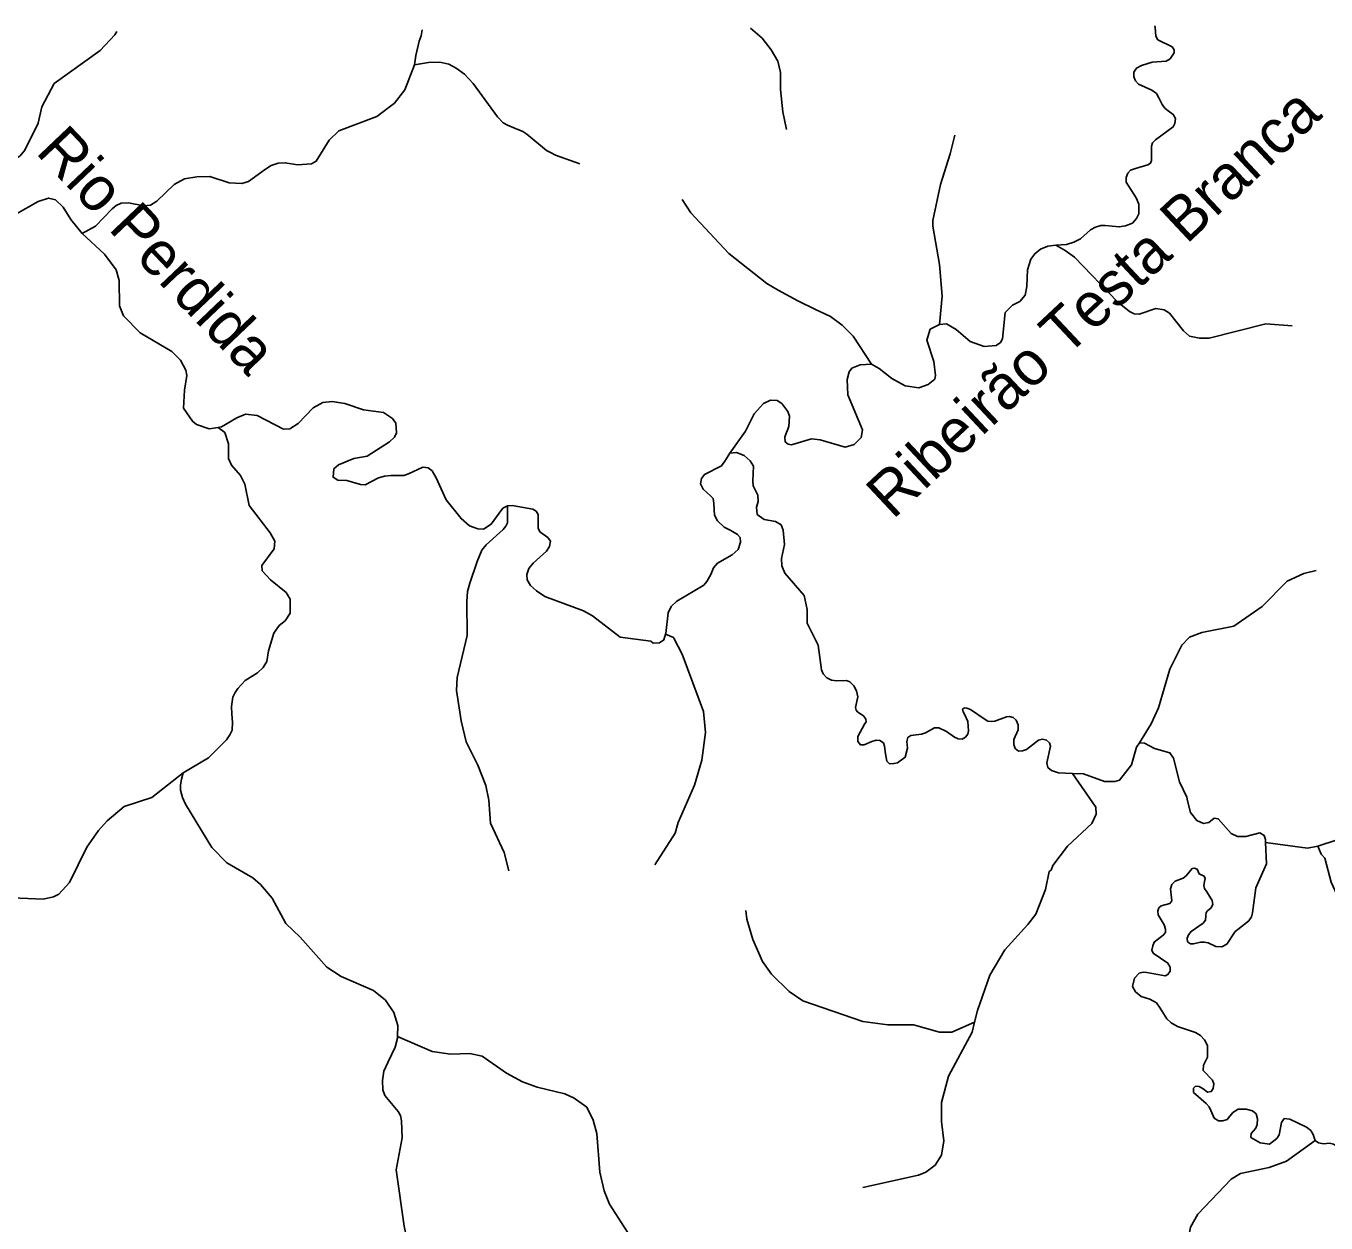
# Model space of a CAD drawing. Extents: x 280.4 to 335.6, y 8893.9 to 8949.5.
# Drawn here: x 297.74 to 303.6, y 8943.96 to 8949.35 of the extents above; entities that cross this region are included whole.
import ezdxf
from ezdxf.enums import TextEntityAlignment as Align

# ---------------------------------------------------------------- set-up
doc = ezdxf.new("R2010")
doc.units = 0
doc.header["$LTSCALE"] = 0.064
doc.linetypes.add('LONG_DASHED', pattern=[7.5, 6, -1.5])
doc.layers.add('61', color=7, linetype='Continuous')
doc.layers.add('7', color=7, linetype='Continuous', lineweight=25)
doc.layers.add('9', color=7, linetype='LONG_DASHED', lineweight=25)

msp = doc.modelspace()

# ---------------------------------------------------------------- linework, layer by layer
at = {"layer": '7'}
for points in [[(299.5241, 8949.3374), (299.5195, 8949.3102), (299.5103, 8949.2865), (299.4945, 8949.2218), (299.4892, 8949.1796)], [(301.0024, 8949.3451), (301.0551, 8949.2996), (301.096, 8949.2471), (301.126, 8949.1957), (301.1383, 8949.1453), (301.1384, 8949.0678), (301.1479, 8948.9676), (301.1656, 8948.8887)], [(302.8247, 8949.3546), (302.8253, 8949.3481), (302.8289, 8949.3093), (302.8381, 8949.2923), (302.9021, 8949.2608), (302.9118, 8949.2476), (302.9114, 8949.2338), (302.8931, 8949.2072), (302.8763, 8949.1968), (302.8127, 8949.1923), (302.764, 8949.1772), (302.7415, 8949.1648), (302.7297, 8949.1463), (302.7296, 8949.1256), (302.7376, 8949.107), (302.7508, 8949.092), (302.8107, 8949.065), (302.8315, 8949.0507), (302.8428, 8949.0305), (302.8573, 8949.0004), (302.8696, 8948.9844), (302.8843, 8948.9721), (302.9078, 8948.9564), (302.9175, 8948.9378), (302.9151, 8948.9154), (302.9076, 8948.9006), (302.8278, 8948.842), (302.8146, 8948.8288), (302.8094, 8948.8137), (302.8093, 8948.7487), (302.8045, 8948.7364), (302.7933, 8948.7291), (302.7368, 8948.7127), (302.7148, 8948.7045), (302.7025, 8948.6911), (302.6952, 8948.6725), (302.6947, 8948.6504), (302.7404, 8948.5805), (302.7517, 8948.5518), (302.752, 8948.5078), (302.7417, 8948.4867), (302.7236, 8948.4661), (302.693, 8948.4542), (302.664, 8948.449), (302.6009, 8948.4551), (302.5814, 8948.4552), (302.5569, 8948.4487), (302.5343, 8948.4366), (302.4902, 8948.395), (302.4601, 8948.3799), (302.4259, 8948.3698), (302.3789, 8948.3676)], [(299.4892, 8949.1796), (299.445, 8949.0668), (299.3997, 8949.0072), (299.32, 8948.9462), (299.1482, 8948.8825), (299.1051, 8948.8403), (299.0466, 8948.7451), (299.0252, 8948.7331), (298.9625, 8948.7287), (298.907, 8948.7382), (298.8748, 8948.7363), (298.8435, 8948.7266), (298.8185, 8948.7098), (298.7417, 8948.6539), (298.7115, 8948.6455), (298.654, 8948.6474), (298.5667, 8948.6759), (298.5092, 8948.6757), (298.4533, 8948.6662), (298.407, 8948.6408), (298.328, 8948.5651), (298.3005, 8948.5477), (298.2692, 8948.5448), (298.2007, 8948.5581), (298.1682, 8948.5565), (298.145, 8948.5451), (298.1265, 8948.5313), (298.0523, 8948.4526), (297.9925, 8948.4193)], [(300.2342, 8948.7329), (300.1248, 8948.7722), (300.1016, 8948.7842), (300.0839, 8948.7933), (299.9956, 8948.8671), (299.9772, 8948.879), (299.9362, 8948.8961), (299.9082, 8948.9073), (299.8887, 8948.9185), (299.8624, 8948.9452), (299.7528, 8949.0955), (299.7147, 8949.1374), (299.6764, 8949.1651), (299.6435, 8949.1823), (299.6026, 8949.1915), (299.5526, 8949.1906), (299.4892, 8949.1796)], [(301.923, 8948.8629), (301.903, 8948.7789), (301.8587, 8948.6405), (301.8249, 8948.4777), (301.8245, 8948.4527), (301.8539, 8948.2801), (301.866, 8948.1378), (301.8544, 8948.0104)], [(297.9925, 8948.4193), (297.9413, 8948.4829), (297.9057, 8948.5389), (297.8715, 8948.5714), (297.841, 8948.5789), (297.7942, 8948.5639), (297.6934, 8948.5066), (297.6664, 8948.5034), (297.6409, 8948.5177), (297.5781, 8948.6636), (297.5588, 8948.697)], [(300.6954, 8948.5733), (300.7342, 8948.5122), (300.9054, 8948.3298), (301.0766, 8948.1937), (301.1279, 8948.165), (301.2157, 8948.1158), (301.2958, 8948.0778), (301.3638, 8948.0456), (301.4166, 8948.0074), (301.4662, 8947.9578), (301.5477, 8947.8311)], [(298.6049, 8947.5459), (298.5641, 8947.5399), (298.5073, 8947.5597), (298.4887, 8947.5741), (298.4484, 8947.6331), (298.4529, 8947.7134), (298.4642, 8947.7803), (298.4596, 8947.8035), (298.4347, 8947.8494), (298.3964, 8947.8878), (298.2538, 8947.9718), (298.1784, 8948.0492), (298.1606, 8948.0945), (298.1588, 8948.2081), (298.1459, 8948.2567), (298.0922, 8948.3267), (297.9925, 8948.4193)], [(302.3789, 8948.3676), (302.3428, 8948.3632), (302.3088, 8948.349), (302.2837, 8948.3282), (302.2653, 8948.3046), (302.2514, 8948.2561), (302.2482, 8948.1809), (302.24, 8948.1419), (302.2162, 8948.1133), (302.1827, 8948.0967), (302.1495, 8948.0634), (302.1382, 8947.9452), (302.1285, 8947.9281), (302.1094, 8947.9155), (302.0554, 8947.9099), (301.9918, 8947.9329), (301.9299, 8947.9866), (301.8857, 8948.0123), (301.8544, 8948.0104)], [(303.4429, 8948.0039), (303.3246, 8948.0122), (303.07, 8947.9485), (303.0262, 8947.9476), (302.9803, 8947.9577), (302.9531, 8947.9806), (302.8899, 8948.0612), (302.8661, 8948.0759), (302.8284, 8948.0823), (302.7543, 8948.0557), (302.7313, 8948.0579), (302.7099, 8948.0687), (302.6566, 8948.1125), (302.4627, 8948.3134), (302.4205, 8948.3424), (302.3789, 8948.3676)], [(301.8544, 8948.0104), (301.8122, 8947.9884), (301.7976, 8947.9386), (301.8293, 8947.8435), (301.8371, 8947.7804), (301.8331, 8947.7635), (301.804, 8947.74), (301.762, 8947.7244), (301.6991, 8947.7326), (301.6389, 8947.766), (301.5819, 8947.8117), (301.5477, 8947.8311)], [(301.5477, 8947.8311), (301.4972, 8947.8274), (301.46, 8947.8136), (301.4472, 8947.7962), (301.4377, 8947.7618), (301.442, 8947.6924), (301.5077, 8947.5357), (301.5022, 8947.5006), (301.4703, 8947.4683), (301.4293, 8947.4576), (301.3165, 8947.4906), (301.2782, 8947.4939), (301.187, 8947.4677), (301.1722, 8947.4707), (301.1593, 8947.4806), (301.1577, 8947.5041), (301.1752, 8947.5508), (301.1783, 8947.5968), (301.1712, 8947.6179), (301.1436, 8947.6533), (301.1236, 8947.6674), (301.0936, 8947.6683), (301.0619, 8947.6543), (301.0193, 8947.6069), (300.9807, 8947.5293), (300.9103, 8947.4305)], [(299.184, 8947.3067), (299.1431, 8947.3085), (299.1224, 8947.3215), (299.1262, 8947.3601), (299.1472, 8947.3773), (299.2161, 8947.4055), (299.2758, 8947.4161), (299.3762, 8947.4804), (299.3993, 8947.5015), (299.4079, 8947.521), (299.4044, 8947.5657), (299.3894, 8947.5859), (299.3494, 8947.6133), (299.2597, 8947.6257), (299.1753, 8947.654), (299.1177, 8947.6634), (299.0769, 8947.6586), (299.0328, 8947.6335), (298.9646, 8947.564), (298.9281, 8947.5403), (298.8994, 8947.5379), (298.781, 8947.599), (298.7284, 8947.6057), (298.6891, 8947.5896), (298.62, 8947.5481), (298.6049, 8947.5459)], [(298.8402, 8946.8592), (298.8023, 8946.9003), (298.801, 8946.9236), (298.8572, 8946.9992), (298.8593, 8947.0327), (298.8396, 8947.0705), (298.7443, 8947.1942), (298.7254, 8947.2905), (298.7051, 8947.3298), (298.6654, 8947.3759), (298.6518, 8947.4062), (298.6515, 8947.4725), (298.6354, 8947.5227), (298.6049, 8947.5459)], [(300.9103, 8947.4305), (300.8868, 8947.3938), (300.8729, 8947.3729), (300.7952, 8947.3341), (300.7818, 8947.3156), (300.7773, 8947.2917), (300.7901, 8947.2674), (300.8224, 8947.2381), (300.835, 8947.2252), (300.8376, 8947.2038), (300.8411, 8947.1511), (300.8542, 8947.1246), (300.8842, 8947.096), (300.9143, 8947.082), (300.9444, 8947.064), (300.9569, 8947.0496), (300.9575, 8947.0286), (300.948, 8946.9957), (300.9208, 8946.9723), (300.8542, 8946.9338), (300.836, 8946.9127), (300.8248, 8946.8831), (300.8069, 8946.851), (300.7932, 8946.8358), (300.6704, 8946.7635), (300.6448, 8946.7397), (300.6314, 8946.7103), (300.6213, 8946.6167), (300.6205, 8946.6141)], [(301.9825, 8946.221), (301.9857, 8946.1793), (301.9818, 8946.1639), (301.9714, 8946.1508), (301.9571, 8946.1415), (301.9379, 8946.1429), (301.9216, 8946.1508), (301.8852, 8946.1761), (301.8507, 8946.1931), (301.8313, 8946.192), (301.7906, 8946.1706), (301.7739, 8946.1639), (301.7249, 8946.1572), (301.7123, 8946.1491), (301.7066, 8946.1305), (301.7106, 8946.101), (301.6997, 8946.0601), (301.6651, 8946.0354), (301.6492, 8946.0311), (301.6297, 8946.0295), (301.6178, 8946.0418), (301.6104, 8946.0748), (301.6069, 8946.1099), (301.6017, 8946.1244), (301.5856, 8946.1352), (301.5695, 8946.1362), (301.5494, 8946.1312), (301.5149, 8946.1159), (301.4984, 8946.116), (301.4869, 8946.1309), (301.4858, 8946.1535), (301.5168, 8946.2092), (301.5234, 8946.2199), (301.5218, 8946.2315), (301.5137, 8946.2446), (301.4856, 8946.2644), (301.4783, 8946.2725), (301.4765, 8946.2837), (301.4869, 8946.3319), (301.4809, 8946.3586), (301.4687, 8946.382), (301.4504, 8946.4002), (301.4347, 8946.4059), (301.3925, 8946.4045), (301.3672, 8946.4069), (301.3474, 8946.4174), (301.3303, 8946.4361), (301.3224, 8946.4538), (301.3075, 8946.5655), (301.2584, 8946.6641), (301.2582, 8946.7256), (301.2441, 8946.7879), (301.1572, 8946.8897), (301.1435, 8946.9224), (301.1432, 8946.955), (301.1558, 8947.0191), (301.1508, 8947.0829), (301.1411, 8947.1069), (301.1163, 8947.1225), (301.0638, 8947.131), (301.0335, 8947.1532), (301.0296, 8947.1868), (301.0375, 8947.2117), (301.0361, 8947.2413), (301.0154, 8947.2829), (301.0141, 8947.3053), (301.0162, 8947.3715), (301.0021, 8947.3952), (300.974, 8947.4189), (300.9394, 8947.4334), (300.9103, 8947.4305)], [(299.9077, 8947.1921), (299.8873, 8947.1825), (299.8701, 8947.159), (299.8348, 8947.1103), (299.8004, 8947.0869), (299.7743, 8947.0883), (299.7366, 8947.1018), (299.6991, 8947.1349), (299.632, 8947.219), (299.5862, 8947.3182), (299.5683, 8947.3496), (299.5508, 8947.3645), (299.5264, 8947.3671), (299.4619, 8947.3368), (299.4415, 8947.3295), (299.3832, 8947.3292), (299.3543, 8947.3265), (299.3272, 8947.3182), (299.2675, 8947.2878), (299.2454, 8947.2894), (299.184, 8947.3067)], [(299.9145, 8945.5478), (299.8926, 8945.6303), (299.8318, 8945.7622), (299.8235, 8945.8661), (299.8107, 8945.9322), (299.7738, 8946.0248), (299.7215, 8946.1299), (299.6993, 8946.2242), (299.6782, 8946.3608), (299.6817, 8946.4193), (299.7261, 8946.6089), (299.7245, 8946.7614), (299.7285, 8946.8072), (299.738, 8946.8448), (299.7716, 8946.9417), (299.7931, 8946.9927), (299.812, 8947.017), (299.8887, 8947.0858), (299.9008, 8947.1005), (299.9084, 8947.1161), (299.9088, 8947.1368), (299.9077, 8947.1921)], [(300.6205, 8946.6141), (300.6128, 8946.5887), (300.5933, 8946.575), (300.5639, 8946.5745), (300.5533, 8946.5826), (300.4161, 8946.6016), (300.2907, 8946.6976), (300.25, 8946.7203), (300.0765, 8946.784), (300.0387, 8946.8091), (300.0111, 8946.8341), (299.9965, 8946.8591), (299.9949, 8946.8838), (300.0046, 8946.9096), (300.0245, 8946.9336), (300.0838, 8946.9882), (300.0972, 8947.009), (300.1018, 8947.0329), (300.0905, 8947.0493), (300.0541, 8947.0762), (300.0463, 8947.0919), (300.0458, 8947.1533), (300.0367, 8947.1686), (300.0216, 8947.1782), (299.929, 8947.1946), (299.9077, 8947.1921)], [(298.4471, 8945.9897), (298.5611, 8946.0578), (298.6423, 8946.1386), (298.657, 8946.1604), (298.6674, 8946.1819), (298.669, 8946.2158), (298.6657, 8946.2558), (298.6644, 8946.2881), (298.6712, 8946.3301), (298.681, 8946.3513), (298.6928, 8946.3693), (298.7268, 8946.4051), (298.7826, 8946.4402), (298.8073, 8946.4636), (298.8241, 8946.4914), (298.8312, 8946.5398), (298.856, 8946.6185), (298.88, 8946.6536), (298.9067, 8946.6751), (298.9295, 8946.7094), (298.9295, 8946.7726), (298.9106, 8946.8026), (298.8402, 8946.8592)], [(303.5506, 8946.9017), (303.4959, 8946.8874), (303.42, 8946.8538), (303.308, 8946.7388), (303.1802, 8946.6511), (303.0359, 8946.6222), (302.9809, 8946.6002), (302.9461, 8946.5653), (302.8928, 8946.4561), (302.8406, 8946.2818), (302.8079, 8946.2099), (302.7553, 8946.1247)], [(300.5715, 8945.5747), (300.6635, 8945.7179), (300.6764, 8945.7658), (300.751, 8945.9342), (300.7831, 8946.0461), (300.8009, 8946.1714), (300.7909, 8946.2656), (300.6948, 8946.5246), (300.6596, 8946.5937), (300.6558, 8946.5988), (300.6205, 8946.6141)], [(302.4541, 8945.9868), (302.3906, 8945.9893), (302.3591, 8946.0003), (302.3431, 8946.0134), (302.3383, 8946.0351), (302.3548, 8946.1097), (302.3499, 8946.1253), (302.3369, 8946.1371), (302.319, 8946.1408), (302.2998, 8946.1375), (302.2465, 8946.0952), (302.2281, 8946.0887), (302.2097, 8946.0872), (302.1956, 8946.0999), (302.1886, 8946.1176), (302.189, 8946.1391), (302.2081, 8946.1836), (302.2081, 8946.2058), (302.2002, 8946.2264), (302.1863, 8946.2387), (302.1701, 8946.2434), (302.1555, 8946.2416), (302.1034, 8946.2229), (302.0875, 8946.221), (302.0726, 8946.2229), (302.0551, 8946.2333), (301.9934, 8946.275), (301.9772, 8946.2812), (301.9664, 8946.282), (301.9587, 8946.2766), (301.961, 8946.2642), (301.9687, 8946.2514), (301.9825, 8946.221)], [(302.7553, 8946.1247), (302.7422, 8946.1055), (302.7193, 8946.0253), (302.6655, 8945.957), (302.6446, 8945.9511), (302.5978, 8945.9511), (302.5031, 8945.9848), (302.4541, 8945.9868)], [(303.3235, 8945.6764), (303.323, 8945.6891), (303.3173, 8945.7078), (303.2976, 8945.7194), (303.234, 8945.7029), (303.1971, 8945.7025), (303.1683, 8945.7167), (303.1103, 8945.783), (303.0912, 8945.7856), (303.0672, 8945.7656), (303.0437, 8945.761), (303.0143, 8945.775), (302.9859, 8945.8112), (302.9722, 8945.8638), (302.9681, 8945.8796), (302.9361, 8945.9489), (302.9093, 8946.0557), (302.8921, 8946.0802), (302.8224, 8946.0996), (302.7781, 8946.1236), (302.7553, 8946.1247)], [(297.4808, 8945.3688), (297.5627, 8945.4097), (297.6418, 8945.4274), (297.8161, 8945.4199), (297.8633, 8945.4305), (297.8871, 8945.4428), (297.9353, 8945.4953), (298.0135, 8945.6548), (298.0654, 8945.7296), (298.105, 8945.7737), (298.1819, 8945.8375), (298.3065, 8945.8792), (298.4471, 8945.9897)], [(299.4129, 8944.8022), (299.414, 8944.8505), (299.3959, 8944.9095), (299.3588, 8944.965), (299.305, 8945.0085), (299.1591, 8945.0724), (299.0946, 8945.1144), (298.9734, 8945.2497), (298.909, 8945.3111), (298.8486, 8945.4256), (298.796, 8945.4864), (298.7602, 8945.5172), (298.6441, 8945.5841), (298.5765, 8945.6537), (298.4568, 8945.8478), (298.4435, 8945.878), (298.4356, 8945.912), (298.4349, 8945.935), (298.439, 8945.9604), (298.4471, 8945.9897)], [(302.0127, 8944.8665), (302.0255, 8944.9194), (302.0807, 8945.0782), (302.149, 8945.1927), (302.2525, 8945.3057), (302.2885, 8945.3533), (302.332, 8945.4646), (302.349, 8945.5455), (302.3581, 8945.5512), (302.3653, 8945.5714), (302.4306, 8945.6596), (302.5403, 8945.7615), (302.5597, 8945.8029), (302.5594, 8945.8349), (302.4541, 8945.9868)], [(304.1724, 8945.9419), (304.1298, 8945.922), (304.0254, 8945.8922), (303.8683, 8945.8308), (303.8043, 8945.7956), (303.7098, 8945.7262), (303.6459, 8945.6877), (303.5592, 8945.6587)], [(302.998, 8944.5499), (302.9984, 8944.5684), (303.0074, 8944.5774), (303.024, 8944.5759), (303.0429, 8944.5655), (303.0624, 8944.5502), (303.0783, 8944.5535), (303.0877, 8944.5668), (303.0902, 8944.5879), (303.0842, 8944.6054), (303.042, 8944.6491), (303.0436, 8944.6723), (303.0619, 8944.709), (303.0617, 8944.7615), (303.0481, 8944.7867), (303.03, 8944.8062), (303.0073, 8944.8202), (302.9263, 8944.8467), (302.8975, 8944.8635), (302.8783, 8944.8812), (302.8478, 8944.9297), (302.8316, 8944.9527), (302.8015, 8944.9703), (302.7625, 8944.9815), (302.7367, 8945.0035), (302.7237, 8945.0265), (302.733, 8945.0644), (302.7546, 8945.087), (302.7716, 8945.0909), (302.7879, 8945.0901), (302.8705, 8945.0744), (302.8837, 8945.0808), (302.8941, 8945.0953), (302.8938, 8945.1144), (302.8836, 8945.1316), (302.8169, 8945.1778), (302.8116, 8945.1908), (302.8153, 8945.2109), (302.8221, 8945.2271), (302.8624, 8945.2579), (302.8731, 8945.2702), (302.8725, 8945.286), (302.8658, 8945.305), (302.8389, 8945.3499), (302.8373, 8945.3683), (302.8419, 8945.381), (302.8523, 8945.3902), (302.8923, 8945.4003), (302.9012, 8945.4136), (302.8945, 8945.4668), (302.9017, 8945.4867), (302.9162, 8945.5012), (302.9521, 8945.5147), (302.9656, 8945.5251), (302.9921, 8945.5586), (303.0037, 8945.5607), (303.0149, 8945.555), (303.0248, 8945.5345), (303.046, 8945.5235), (303.0519, 8945.5136), (303.0485, 8945.5001), (303.0452, 8945.4822), (303.0485, 8945.4687), (303.0586, 8945.453), (303.0833, 8945.4149), (303.0857, 8945.3969), (303.0766, 8945.3801), (303.0631, 8945.3689), (303.0553, 8945.36), (303.0541, 8945.3454), (303.053, 8945.3252), (303.0429, 8945.3129), (302.988, 8945.2748), (302.9757, 8945.2602), (302.9701, 8945.2444), (302.9712, 8945.2282), (302.9846, 8945.2198), (302.9992, 8945.2198), (303.0302, 8945.2261), (303.0474, 8945.2266), (303.0646, 8945.223), (303.0991, 8945.2077), (303.1264, 8945.2063), (303.1487, 8945.2173), (303.1863, 8945.2746), (303.1979, 8945.2837), (303.2476, 8945.3223), (303.2604, 8945.3409), (303.2652, 8945.3587), (303.2801, 8945.4716), (303.3275, 8945.5801), (303.3235, 8945.6764)], [(303.5592, 8945.6587), (303.512, 8945.6499), (303.3235, 8945.6764)], [(304.3496, 8945.183), (304.259, 8945.2038), (304.1452, 8945.2102), (304.0336, 8945.1962), (303.9233, 8945.2356), (303.76, 8945.3667), (303.6808, 8945.4123), (303.644, 8945.4408), (303.6186, 8945.4963), (303.59, 8945.6057), (303.5738, 8945.6238), (303.5592, 8945.6587)], [(300.982, 8945.37), (300.9867, 8945.3305), (301.0132, 8945.2387), (301.0564, 8945.1398), (301.0979, 8945.0828), (301.1764, 8945.0043), (301.2392, 8944.9625), (301.5085, 8944.8696), (301.6222, 8944.8537), (301.7373, 8944.8537), (301.854, 8944.8217), (301.9101, 8944.8217), (302.0127, 8944.8665)], [(301.5095, 8944.1219), (301.7599, 8944.177), (301.7924, 8944.1911), (301.8343, 8944.2218), (301.8628, 8944.2668), (301.874, 8944.3316), (301.8629, 8944.4194), (301.8629, 8944.5043), (301.8945, 8944.6227), (302.0018, 8944.8217), (302.0127, 8944.8665)], [(299.5114, 8943.843), (299.4826, 8943.8704), (299.4672, 8943.8877), (299.4494, 8943.9189), (299.4426, 8943.9465), (299.4064, 8944.2011), (299.4334, 8944.3444), (299.4307, 8944.4221), (299.4255, 8944.4452), (299.4161, 8944.4634), (299.3701, 8944.5173), (299.3559, 8944.5364), (299.3459, 8944.5619), (299.3447, 8944.6035), (299.3517, 8944.646), (299.3697, 8944.6843), (299.4019, 8944.7532), (299.4127, 8944.7937), (299.4129, 8944.8022)], [(300.8864, 8943.4259), (300.8533, 8943.5268), (300.8236, 8943.5896), (300.7705, 8943.6702), (300.697, 8943.7336), (300.5406, 8943.8303), (300.4482, 8943.9203), (300.3684, 8944.0462), (300.3431, 8944.1068), (300.3245, 8944.1908), (300.3099, 8944.3642), (300.2945, 8944.4245), (300.2656, 8944.4831), (300.209, 8944.5232), (300.1661, 8944.544), (300.0412, 8944.5733), (299.9756, 8944.5969), (299.9031, 8944.6366), (299.7948, 8944.7129), (299.7383, 8944.7257), (299.6519, 8944.7226), (299.569, 8944.7347), (299.4129, 8944.8022)], [(303.5464, 8944.3335), (303.5374, 8944.3606), (303.5273, 8944.3774), (303.5073, 8944.3937), (303.4322, 8944.4294), (303.4077, 8944.4327), (303.3954, 8944.4144), (303.3853, 8944.3585), (303.374, 8944.342), (303.3415, 8944.3167), (303.299, 8944.3229), (303.2574, 8944.3466), (303.2579, 8944.3645), (303.2795, 8944.3883), (303.286, 8944.4059), (303.2875, 8944.4314), (303.2815, 8944.4529), (303.2649, 8944.466), (303.2363, 8944.475), (303.2, 8944.4743), (303.1766, 8944.4594), (303.1501, 8944.427), (303.1309, 8944.4223), (303.1119, 8944.4221), (303.0917, 8944.4344), (303.0767, 8944.4675), (303.0692, 8944.4841), (303.0556, 8944.4991), (302.998, 8944.5499)], [(302.7885, 8943.429), (302.7925, 8943.4401), (302.8109, 8943.4599), (302.838, 8943.4776), (302.8825, 8943.5066), (302.9517, 8943.5288), (302.9779, 8943.5476), (303.0042, 8943.5866), (302.9729, 8943.8286), (302.9759, 8943.8934), (302.9854, 8943.943), (303.0186, 8944.001), (303.1679, 8944.1594), (303.2102, 8944.1837), (303.3389, 8944.2108), (303.4174, 8944.2404), (303.503, 8944.3016), (303.5464, 8944.3335)], [(303.893, 8944.1339), (303.837, 8944.1423), (303.8155, 8944.1594), (303.8171, 8944.1909), (303.8551, 8944.246), (303.855, 8944.2703), (303.844, 8944.2904), (303.8189, 8944.3004), (303.7904, 8944.2997), (303.7692, 8944.2883), (303.7262, 8944.2416), (303.709, 8944.2311), (303.6907, 8944.2318), (303.6759, 8944.2447), (303.6635, 8944.2722), (303.6435, 8944.3069), (303.6292, 8944.3169), (303.6111, 8944.3215), (303.584, 8944.3185), (303.5615, 8944.323), (303.5464, 8944.3335)]]:
    msp.add_lwpolyline(points, dxfattribs=at)
at = {"layer": '9'}
msp.add_lwpolyline([(298.1483, 8949.33), (298.1391, 8949.3154), (298.0725, 8949.2439), (297.8659, 8949.0957), (297.8105, 8948.9908), (297.7937, 8948.9173), (297.7339, 8948.7949), (297.7123, 8948.7698), (297.6582, 8948.7341), (297.5588, 8948.697)], dxfattribs=at)

# ---------------------------------------------------------------- texts
at = {"layer": '61'}
for s, rotation, p in [('Ribeirão Testa Branca', 43.152, (302.6143, 8948.0375)), ('Rio Perdida', 313.565, (298.2591, 8948.2779))]:
    msp.add_text(s, height=0.2, rotation=rotation, dxfattribs=at).set_placement(p, align=Align.CENTER)

doc.saveas('drawing.dxf')
